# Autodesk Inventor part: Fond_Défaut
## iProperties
Shininess: 64.0
Length Units: 11269
Angle Units: 11279
Time Units: 11290
Mass Units: 11283
Length Display Precision: 3
Angle Display Precision: 2
Compacted: True
Part Number: Fond_Défaut
Document SubType Name: Modeling
Created: 2006-01
Material: Par défaut
Designer: riri
Density: 0.0
Volumn: 0.0
Area: 0.0
PropertySet Name: Model Information
Control State: 0
Master: False
Checked Out: False
Author: riri
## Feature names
1. Base1
